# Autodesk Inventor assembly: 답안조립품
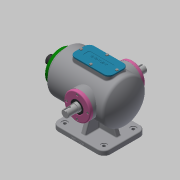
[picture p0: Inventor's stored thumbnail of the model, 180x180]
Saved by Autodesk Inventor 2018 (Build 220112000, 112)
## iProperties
Created: 2021-11
Part Number: 답안조립품
Material: 일반
Document SubType Name: Assembly
Designer: home
Author: home
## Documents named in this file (14)
- C:\Users\home\Desktop\711106V1037\답안조립품.iam
- C:\Users\home\Desktop\711106V1037\본체.ipt
- C:\Users\home\Desktop\711106V1037\축 커버.ipt
- C:\Users\home\Desktop\711106V1037\베어링 6205.ipt
- 베어링 6205.ipt
- C:\Users\home\Desktop\711106V1037\오일실.ipt
- 오일실.ipt
- C:\Users\home\Desktop\711106V1037\편심축.ipt
- C:\Users\home\Desktop\711106V1037\슬라이드.ipt
- C:\Users\home\Desktop\711106V1037\부시.ipt
- C:\Users\home\Desktop\711106V1037\슬라이드 커버.ipt
- C:\Users\home\Desktop\711106V1037\상부커버.ipt
- C:\Users\home\Desktop\711106V1037\육각머리볼트 M4.ipt
- C:\Users\home\Desktop\711106V1037\볼트 M4x0.7.ipt
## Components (12 placed, 1 different names)
1. M4x0.7:1
2. M4x0.7:2
3. M4x0.7:4
4. M4x0.7:5
5. M4x0.7:6
6. M4x0.7:7
7. M4x0.7:8
8. M4x0.7:9
9. M4x0.7:3
10. M4x0.7:10
11. M4x0.7:11
12. M4x0.7:12
